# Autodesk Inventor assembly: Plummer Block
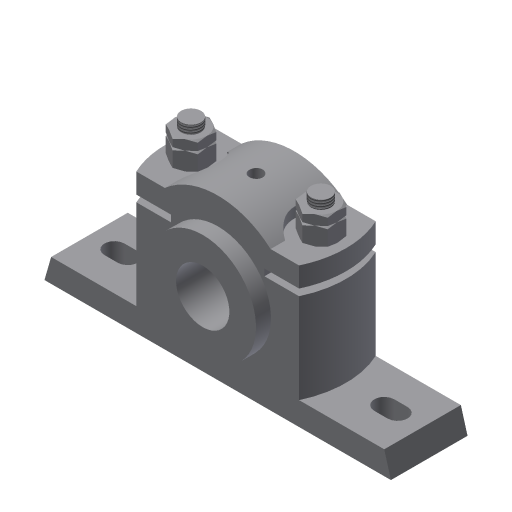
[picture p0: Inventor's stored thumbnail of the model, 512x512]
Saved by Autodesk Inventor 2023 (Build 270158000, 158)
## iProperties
Created: 2011-07
Part Number: Plummer Block
Document SubType Name: Assembly
Designer: CadCim
Author: CadCim
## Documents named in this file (7)
- D:\PROJECTS\Project 2022\Autodesk Inventor For Professional 2023\RESOURCES INVENTOR 2023\RESOURCES INVENTOR 2023\Inventor_2023_tut\Inventor_2023_tut\c09_Inv_2023_tut\c09_Inv_2023_tut\c09_Inv_tut_2023\c09_tut02_inv\Plummer Block\Plummer Block.iam
- D:\PROJECTS\Project 2022\Autodesk Inventor For Professional 2023\RESOURCES INVENTOR 2023\RESOURCES INVENTOR 2023\Inventor_2023_tut\Inventor_2023_tut\c09_Inv_2023_tut\c09_Inv_2023_tut\c09_Inv_tut_2023\c09_tut02_inv\Plummer Block\Casting.ipt
- D:\PROJECTS\Project 2022\Autodesk Inventor For Professional 2023\RESOURCES INVENTOR 2023\RESOURCES INVENTOR 2023\Inventor_2023_tut\Inventor_2023_tut\c09_Inv_2023_tut\c09_Inv_2023_tut\c09_Inv_tut_2023\c09_tut02_inv\Plummer Block\Brasses.ipt
- D:\PROJECTS\Project 2022\Autodesk Inventor For Professional 2023\RESOURCES INVENTOR 2023\RESOURCES INVENTOR 2023\Inventor_2023_tut\Inventor_2023_tut\c09_Inv_2023_tut\c09_Inv_2023_tut\c09_Inv_tut_2023\c09_tut02_inv\Plummer Block\Cap.ipt
- D:\PROJECTS\Project 2022\Autodesk Inventor For Professional 2023\RESOURCES INVENTOR 2023\RESOURCES INVENTOR 2023\Inventor_2023_tut\Inventor_2023_tut\c09_Inv_2023_tut\c09_Inv_2023_tut\c09_Inv_tut_2023\c09_tut02_inv\Plummer Block\Bolt.ipt
- D:\PROJECTS\Project 2022\Autodesk Inventor For Professional 2023\RESOURCES INVENTOR 2023\RESOURCES INVENTOR 2023\Inventor_2023_tut\Inventor_2023_tut\c09_Inv_2023_tut\c09_Inv_2023_tut\c09_Inv_tut_2023\c09_tut02_inv\Plummer Block\Nut.ipt
- D:\PROJECTS\Project 2022\Autodesk Inventor For Professional 2023\RESOURCES INVENTOR 2023\RESOURCES INVENTOR 2023\Inventor_2023_tut\Inventor_2023_tut\c09_Inv_2023_tut\c09_Inv_2023_tut\c09_Inv_tut_2023\c09_tut02_inv\Plummer Block\locknut.ipt
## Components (9 placed, 6 different names)
1. Casting:1 — Mate:1, Mate:2, Insert:1, Angle:1, Insert:2, Angle:2
2. Brasses:1 — Mate:1, Mate:2, Mate:3, Mate:4
3. Cap:1 — Mate:3, Mate:4, Insert:3, Insert:4
4. Bolt:1 — Insert:1, Angle:1
5. Bolt:2 — Insert:2, Angle:2
6. Nut.:4 — Insert:3, Insert:5, Angle:4
7. Nut.:5 — Insert:4, Insert:6, Angle:3
8. locknut:1 — Insert:5, Angle:4
9. locknut:2 — Insert:6, Angle:3
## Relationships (14: Insert 6, Mate 4, Angle 4)
- Mate:1: Casting:1 ↔ Brasses:1
- Mate:2: Casting:1 ↔ Brasses:1
- Mate:3: Brasses:1 ↔ Cap:1
- Mate:4: Brasses:1 ↔ Cap:1
- Insert:1: Casting:1 ↔ Bolt:1
- Angle:1: Casting:1 ↔ Bolt:1
- Insert:2: Casting:1 ↔ Bolt:2
- Angle:2: Casting:1 ↔ Bolt:2
- Insert:3: Cap:1 ↔ Nut.:4
- Insert:4: Cap:1 ↔ Nut.:5
- Insert:5: Nut.:4 ↔ locknut:1
- Insert:6: Nut.:5 ↔ locknut:2
- Angle:3: Nut.:5 ↔ locknut:2
- Angle:4: Nut.:4 ↔ locknut:1
